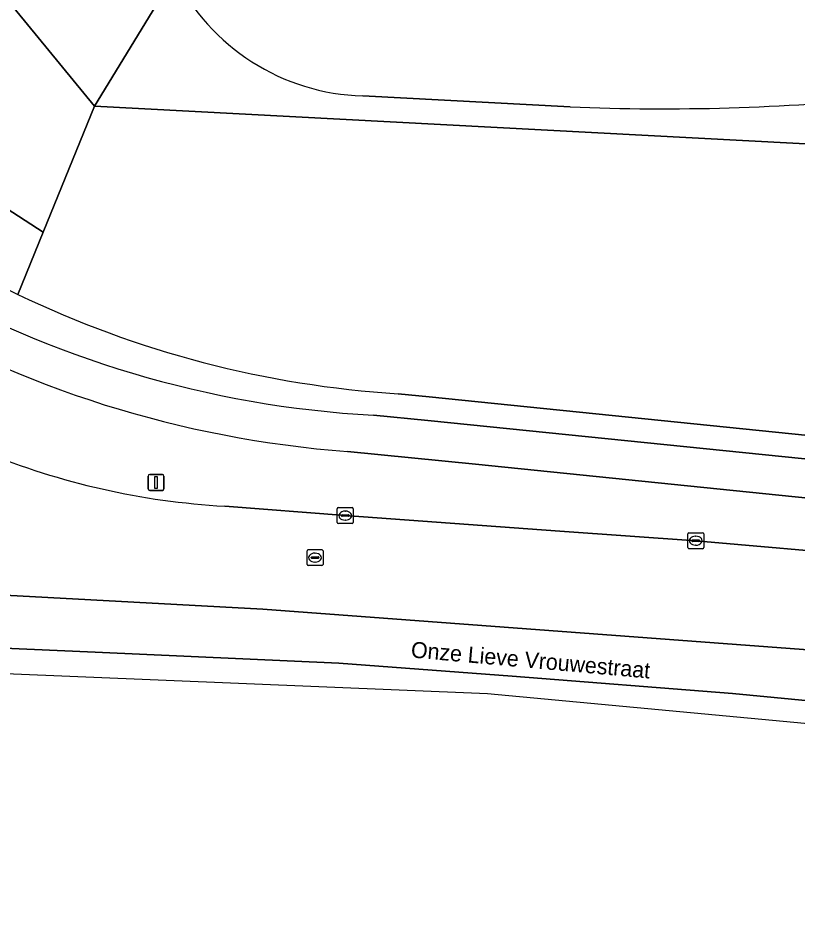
# Model space of a CAD drawing. Extents: x 161758 to 162722, y 384793 to 385405.
# Drawn here: x 161885.6 to 161934.4, y 384850.8 to 384906.8 of the extents above; entities that cross this region are included whole.
import ezdxf

# ---------------------------------------------------------------- set-up
doc = ezdxf.new("R2010")
doc.units = 0
for name, color, linetype in [('IMGEO_Berm_groen', 7, 'Continuous'), ('IMGEO_Erf', 7, 'Continuous'), ('IMGEO_Fietspad_open', 7, 'Continuous'), ('IMGEO_Grasland_overig', 7, 'Continuous'), ('IMGEO_Groenvoorziening', 7, 'Continuous'), ('IMGEO_Hek', 7, 'Continuous'), ('IMGEO_Kolk', 7, 'Continuous'), ('IMGEO_Lichtmast', 7, 'Continuous'), ('IMGEO_Openbare_ruimte_label', 7, 'Continuous'), ('IMGEO_Rijbaan_lokaal_open', 7, 'Continuous'), ('IMGEO_Rijbaan_regionaal_gesloten', 7, 'Continuous'), ('IMGEO_Voetpad_open', 7, 'Continuous')]:
    doc.layers.add(name, color=color, linetype=linetype)

msp = doc.modelspace()

# ---------------------------------------------------------------- linework, layer by layer
at = {"layer": 'IMGEO_Berm_groen'}
for points in [[(162006.513, 384869.453), (161914.243, 384878.869), (161906.236, 384879.67)], [(161898.542, 384876.248), (161906.087, 384875.658), (161919.526, 384874.676), (161928.024, 384874.09), (161939.016, 384873.121), (161949.945, 384872.108), (161969.946, 384870.078), (161971.826, 384869.887), (161993.707, 384867.657), (162012.89, 384865.622), (162015.558, 384865.321)]]:
    msp.add_lwpolyline(points, dxfattribs=at)
for centre, radius, start, end in [((161911.283, 384946.965), 67.484, 213.26832, 265.71076), ((161901.155, 384922.767), 46.592, 247.6945, 266.7853)]:
    msp.add_arc(centre, radius, start, end, dxfattribs=at)
at = {"layer": 'IMGEO_Erf'}
msp.add_lwpolyline([(161880.923, 385119.329), (161863.287, 385003.273), (161862.79, 385000), (161854.635, 384944.828), (161890.389, 384901.27), (161895.384, 384909.442)], dxfattribs=at)
at = {"layer": 'IMGEO_Fietspad_open'}
for points in [[(162067.483, 384866.056), (162006.647, 384871.905), (161911.253, 384881.598), (161907.851, 384881.941)], [(161906.236, 384879.67), (161914.243, 384878.869), (162006.513, 384869.453), (162058.328, 384864.505), (162070.849, 384863.309), (162087.851, 384861.724)]]:
    msp.add_lwpolyline(points, dxfattribs=at)
for centre, radius, start, end in [((161911.392, 384946.969), 65.124, 213.21933, 266.8833), ((161911.283, 384946.965), 67.484, 213.26832, 265.71076)]:
    msp.add_arc(centre, radius, start, end, dxfattribs=at)
at = {"layer": 'IMGEO_Grasland_overig'}
for points in [[(161895.384, 384909.442), (161890.389, 384901.27), (161940.395, 384898.63), (161940.072, 384901.813)], [(161920.156, 384901.23), (161907.181, 384901.909)]]:
    msp.add_lwpolyline(points, dxfattribs=at)
for centre, radius, start, end in [((161907.585, 384915.545), 13.642, 206.5745, 268.3048), ((161926.059, 385040.036), 138.931, 267.56473, 275.78874)]:
    msp.add_arc(centre, radius, start, end, dxfattribs=at)
at = {"layer": 'IMGEO_Groenvoorziening'}
for points in [[(161892.743, 385260.68), (161890.539, 385233.713), (161888.572, 385218.345), (161891.617, 385217.57), (161876.429, 385120.298), (161873.599, 385102.176), (161860.843, 385019.372), (161853.315, 384968.451), (161850.889, 384943.599), (161852.833, 384935.577), (161860.083, 384917.83), (161874.638, 384901.508), (161887.186, 384893.396), (161890.389, 384901.27), (161854.635, 384944.828), (161862.79, 385000), (161863.287, 385003.273), (161880.923, 385119.329), (161887.975, 385165.729), (161892.13, 385191.383), (161913.18, 385282.726), (161913.347, 385283.925), (161913.577, 385286.213)], [(161885.599, 384889.495), (161887.186, 384893.396), (161874.638, 384901.508), (161860.083, 384917.83), (161852.833, 384935.577), (161850.889, 384943.599), (161853.315, 384968.451), (161860.843, 385019.372), (161873.599, 385102.176), (161876.429, 385120.298), (161891.617, 385217.57)], [(162101.739, 384890.234), (162071.509, 384891.825), (162025.753, 384894.111), (162013.578, 384894.76), (162000, 384895.483), (161940.395, 384898.63), (161890.389, 384901.27), (161887.186, 384893.396), (161885.599, 384889.495)], [(161909.399, 384883.283), (161911.336, 384883.087), (162006.629, 384873.371), (162069.134, 384867.379), (162085.792, 384865.801)]]:
    msp.add_lwpolyline(points, dxfattribs=at)
for centre, radius, start, end in [((161913.421, 384947.359), 64.206, 212.83252, 244.32073), ((161913.42, 384947.386), 64.229, 244.33236, 266.411)]:
    msp.add_arc(centre, radius, start, end, dxfattribs=at)
at = {"layer": 'IMGEO_Hek'}
for points in [[(161890.389, 384901.27), (161854.635, 384944.828), (161862.79, 385000)], [(161940.395, 384898.63), (161890.389, 384901.27)]]:
    msp.add_lwpolyline(points, dxfattribs=at)
at = {"layer": 'IMGEO_Kolk'}
for p, q in [((161905.586, 384875.232), (161905.586, 384876.084)), ((161905.661, 384876.158), (161906.513, 384876.158)), ((161905.888, 384875.701), (161906.286, 384875.701)), ((161906.074, 384875.938), (161906.099, 384875.938)), ((161906.587, 384876.084), (161906.587, 384875.232)), ((161906.513, 384875.158), (161905.661, 384875.158)), ((161905.845, 384875.652), (161905.845, 384875.664)), ((161906.283, 384875.615), (161905.885, 384875.615)), ((161906.097, 384875.378), (161906.072, 384875.378)), ((161906.329, 384875.664), (161906.329, 384875.652)), ((161927.598, 384874.59), (161928.45, 384874.59)), ((161927.523, 384873.664), (161927.523, 384874.516)), ((161927.782, 384874.084), (161927.782, 384874.096)), ((161928.22, 384874.047), (161927.822, 384874.047)), ((161927.825, 384874.133), (161928.223, 384874.133)), ((161928.011, 384874.37), (161928.036, 384874.37)), ((161928.266, 384874.096), (161928.266, 384874.084)), ((161928.524, 384874.516), (161928.524, 384873.664)), ((161903.694, 384872.603), (161903.694, 384873.455)), ((161903.769, 384873.529), (161904.621, 384873.529)), ((161904.695, 384873.455), (161904.695, 384872.603)), ((161928.45, 384873.59), (161927.598, 384873.59)), ((161928.034, 384873.81), (161928.009, 384873.81)), ((161903.953, 384873.023), (161903.953, 384873.035)), ((161904.391, 384872.986), (161903.993, 384872.986)), ((161903.996, 384873.072), (161904.394, 384873.072)), ((161904.182, 384873.309), (161904.207, 384873.309)), ((161904.437, 384873.035), (161904.437, 384873.023)), ((161904.621, 384872.529), (161903.769, 384872.529)), ((161904.205, 384872.749), (161904.18, 384872.749))]:
    msp.add_line(p, q, dxfattribs=at)
for points in [[(161905.586, 384875.232), (161905.586, 384876.084)], [(161905.661, 384876.158), (161906.513, 384876.158)], [(161906.587, 384876.084), (161906.587, 384875.232)], [(161906.513, 384875.158), (161905.661, 384875.158)], [(161927.598, 384874.59), (161928.45, 384874.59)], [(161927.523, 384873.664), (161927.523, 384874.516)], [(161928.524, 384874.516), (161928.524, 384873.664)], [(161903.694, 384872.603), (161903.694, 384873.455)], [(161903.769, 384873.529), (161904.621, 384873.529)], [(161904.695, 384873.455), (161904.695, 384872.603)], [(161928.45, 384873.59), (161927.598, 384873.59)], [(161904.621, 384872.529), (161903.769, 384872.529)]]:
    msp.add_lwpolyline(points, dxfattribs=at)
for centre, radius, start, end in [((161905.663, 384876.082), 0.0765, 91.552, 178.448), ((161905.663, 384876.082), 0.0765, 91.552, 178.448), ((161905.885, 384875.661), 0.0403, 85.8775, 175.7526), ((161906.29, 384875.663), 0.0386, 1.7309, 96.639), ((161906.511, 384876.082), 0.0765, 1.552, 88.448), ((161906.511, 384876.082), 0.0765, 1.552, 88.448), ((161905.663, 384875.234), 0.0765, 181.552, 268.448), ((161905.663, 384875.234), 0.0765, 181.552, 268.448), ((161905.882, 384875.651), 0.0366, 178.938, 274.7102), ((161906.286, 384875.658), 0.043, 264.8664, 352.4533), ((161906.511, 384875.234), 0.0765, 271.552, 358.448), ((161906.511, 384875.234), 0.0765, 271.552, 358.448), ((161927.6, 384874.514), 0.0765, 91.552, 178.448), ((161927.6, 384874.514), 0.0765, 91.552, 178.448), ((161928.448, 384874.514), 0.0765, 1.552, 88.448), ((161928.448, 384874.514), 0.0765, 1.552, 88.448), ((161927.822, 384874.093), 0.0403, 85.8775, 175.7526), ((161927.819, 384874.083), 0.0366, 178.938, 274.7102), ((161928.223, 384874.09), 0.043, 264.8664, 352.4533), ((161928.227, 384874.095), 0.0386, 1.7309, 96.639), ((161903.771, 384873.453), 0.0765, 91.552, 178.448), ((161903.771, 384873.453), 0.0765, 91.552, 178.448), ((161904.619, 384873.453), 0.0765, 1.552, 88.448), ((161904.619, 384873.453), 0.0765, 1.552, 88.448), ((161927.6, 384873.666), 0.0765, 181.552, 268.448), ((161927.6, 384873.666), 0.0765, 181.552, 268.448), ((161928.448, 384873.666), 0.0765, 271.552, 358.448), ((161928.448, 384873.666), 0.0765, 271.552, 358.448), ((161903.993, 384873.032), 0.0403, 85.8775, 175.7526), ((161903.99, 384873.022), 0.0366, 178.938, 274.7102), ((161904.394, 384873.029), 0.043, 264.8664, 352.4533), ((161904.398, 384873.034), 0.0386, 1.7309, 96.639), ((161903.771, 384872.605), 0.0765, 181.552, 268.448), ((161903.771, 384872.605), 0.0765, 181.552, 268.448), ((161904.619, 384872.605), 0.0765, 271.552, 358.448), ((161904.619, 384872.605), 0.0765, 271.552, 358.448)]:
    msp.add_arc(centre, radius, start, end, dxfattribs=at)
for centre, major_axis, ratio, start_param, end_param in [((161906.073, 384875.658), (-0.387, 0.002), 0.722429, 4.712389, 7.853982), ((161906.098, 384875.658), (-0.39, 0.002), 0.717154, 1.570796, 4.712389), ((161928.01, 384874.09), (-0.387, 0.002), 0.722429, 4.712389, 7.853982), ((161928.035, 384874.09), (-0.39, 0.002), 0.717154, 1.570796, 4.712389), ((161904.181, 384873.029), (-0.387, 0.002), 0.722429, 4.712389, 7.853982), ((161904.206, 384873.029), (-0.39, 0.002), 0.717154, 1.570796, 4.712389)]:
    msp.add_ellipse(centre, major_axis=major_axis, ratio=ratio, start_param=start_param, end_param=end_param, dxfattribs=at)
at = {"layer": 'IMGEO_Lichtmast'}
for p, q in [((161893.751, 384877.333), (161893.751, 384878.133)), ((161893.751, 384878.133), (161893.751, 384877.333)), ((161893.851, 384878.233), (161894.641, 384878.233)), ((161894.641, 384878.233), (161893.851, 384878.233)), ((161894.741, 384878.133), (161894.741, 384877.333)), ((161894.741, 384877.333), (161894.741, 384878.133)), ((161894.641, 384877.233), (161893.851, 384877.233)), ((161893.851, 384877.233), (161894.641, 384877.233))]:
    msp.add_line(p, q, dxfattribs=at)
msp.add_lwpolyline([(161894.171, 384878.108), (161894.321, 384878.108), (161894.321, 384877.358), (161894.171, 384877.358), (161894.171, 384878.108)], dxfattribs=at)
for centre, start, end in [((161893.851, 384878.133), 90, 180), ((161893.851, 384878.133), 90, 180), ((161894.641, 384878.133), 0, 90), ((161894.641, 384878.133), 360, 90), ((161893.851, 384877.333), 180, 270), ((161893.851, 384877.333), 180, 270), ((161894.641, 384877.333), 270, 0), ((161894.641, 384877.333), 270, 0)]:
    msp.add_arc(centre, 0.1, start, end, dxfattribs=at)
at = {"layer": 'IMGEO_Rijbaan_lokaal_open'}
for points in [[(161907.181, 384901.909), (161920.156, 384901.23)], [(162015.558, 384865.321), (162012.89, 384865.622), (161993.707, 384867.657), (161971.826, 384869.887), (161969.946, 384870.078), (161949.945, 384872.108), (161939.016, 384873.121), (161928.024, 384874.09), (161919.526, 384874.676), (161906.087, 384875.658), (161898.542, 384876.248)], [(161884.779, 384870.687), (161900.935, 384869.807), (161935.339, 384867.25), (161968.205, 384864.005), (162017.318, 384858.792), (162045.97, 384856.082), (162098.216, 384850.795)]]:
    msp.add_lwpolyline(points, dxfattribs=at)
for centre, radius, start, end in [((161907.585, 384915.545), 13.642, 206.5745, 268.3048), ((161926.059, 385040.036), 138.931, 267.56473, 275.78874), ((161901.155, 384922.767), 46.592, 247.6945, 266.7853)]:
    msp.add_arc(centre, radius, start, end, dxfattribs=at)
at = {"layer": 'IMGEO_Rijbaan_regionaal_gesloten'}
for points in [[(161935.339, 384867.25), (161900.935, 384869.807), (161884.779, 384870.687), (161883.315, 384870.739), (161880.655, 384870.853), (161841.023, 384872.547), (161839.138, 384872.625), (161831.784, 384872.931), (161831.09, 384872.954), (161829.684, 384872.967), (161828.527, 384869.772), (161828.532, 384869.772), (161845.341, 384869.071), (161871.886, 384867.92), (161890.432, 384867.121), (161905.679, 384866.421), (161916.527, 384865.621), (161930.324, 384864.521), (161942.922, 384863.321)], [(161942.922, 384863.321), (161930.324, 384864.521), (161916.527, 384865.621), (161905.679, 384866.421), (161890.432, 384867.121), (161871.886, 384867.92), (161845.341, 384869.071), (161828.532, 384869.772), (161828.527, 384869.772), (161828.332, 384869.179), (161827.989, 384868.136), (161914.995, 384864.529), (161989.003, 384857.616)]]:
    msp.add_lwpolyline(points, dxfattribs=at)
at = {"layer": 'IMGEO_Voetpad_open'}
for points in [[(162006.629, 384873.371), (161911.336, 384883.087), (161909.399, 384883.283)], [(161907.851, 384881.941), (161911.253, 384881.598), (162006.647, 384871.905), (162067.483, 384866.056), (162087.213, 384864.2)]]:
    msp.add_lwpolyline(points, dxfattribs=at)
for centre, radius, start, end in [((161913.421, 384947.359), 64.206, 212.83252, 244.32073), ((161911.392, 384946.969), 65.124, 213.21933, 266.8833), ((161913.42, 384947.386), 64.229, 244.33236, 266.411)]:
    msp.add_arc(centre, radius, start, end, dxfattribs=at)

# ---------------------------------------------------------------- texts
at = {"layer": 'IMGEO_Openbare_ruimte_label'}
msp.add_text('Onze Lieve Vrouwestraat', height=1, rotation=354.9508, dxfattribs=at).set_placement((161910.168, 384866.79))

doc.saveas('drawing.dxf')
